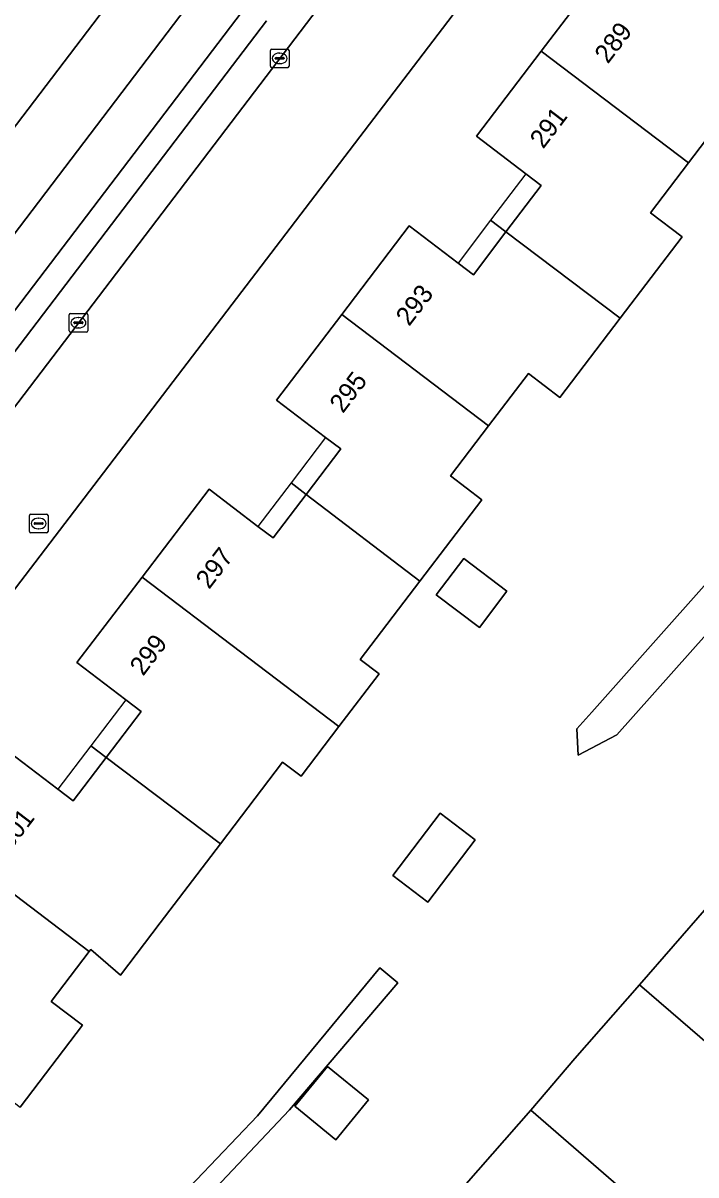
# Model space of a CAD drawing. Extents: x 158472 to 159562, y 388525 to 389606.
# Drawn here: x 158756 to 158792.1, y 388915.3 to 388977 of the extents above; entities that cross this region are included whole.
import ezdxf

# ---------------------------------------------------------------- set-up
doc = ezdxf.new("R2010")
doc.units = 0
for name, color, linetype in [('IMGEO_Berm_groen', 7, 'Continuous'), ('IMGEO_Brandkraan', 7, 'Continuous'), ('IMGEO_Erf', 7, 'Continuous'), ('IMGEO_Kolk', 7, 'Continuous'), ('IMGEO_Pand', 7, 'Continuous'), ('IMGEO_Pand_nummerreeks', 7, 'Continuous'), ('IMGEO_Pand_overbouw', 7, 'Continuous'), ('IMGEO_Parkeervlak_open', 7, 'Continuous'), ('IMGEO_Rijbaan_lokaal_gesloten', 7, 'Continuous'), ('IMGEO_Rijbaan_lokaal_open', 7, 'Continuous'), ('IMGEO_Voetpad_open', 7, 'Continuous')]:
    doc.layers.add(name, color=color, linetype=linetype)

msp = doc.modelspace()

# ---------------------------------------------------------------- linework, layer by layer
at = {"layer": 'IMGEO_Berm_groen'}
msp.add_lwpolyline([(158769.87, 388990.274), (158765.967, 388993.384), (158762.193, 388988.396), (158743.945, 388964.31), (158727.97, 388943.305), (158723.001, 388936.936), (158712.518, 388923.153), (158710.767, 388920.221), (158714.484, 388917.523), (158716.222, 388919.791)], close=True, dxfattribs=at)
at = {"layer": 'IMGEO_Brandkraan'}
for p, q in [((158756.362, 388949.789), (158756.362, 388950.641)), ((158756.437, 388950.715), (158757.289, 388950.715)), ((158756.85, 388950.495), (158756.875, 388950.495)), ((158757.363, 388950.641), (158757.363, 388949.789)), ((158756.621, 388950.209), (158756.621, 388950.221)), ((158757.059, 388950.172), (158756.661, 388950.172)), ((158756.664, 388950.258), (158757.062, 388950.258)), ((158756.873, 388949.935), (158756.848, 388949.935)), ((158757.105, 388950.221), (158757.105, 388950.209)), ((158757.289, 388949.715), (158756.437, 388949.715))]:
    msp.add_line(p, q, dxfattribs=at)
for points in [[(158756.362, 388949.789), (158756.362, 388950.641)], [(158756.437, 388950.715), (158757.289, 388950.715)], [(158757.363, 388950.641), (158757.363, 388949.789)], [(158757.289, 388949.715), (158756.437, 388949.715)]]:
    msp.add_lwpolyline(points, dxfattribs=at)
for centre, radius, start, end in [((158756.439, 388950.639), 0.0765, 91.55205, 178.44795), ((158756.439, 388950.639), 0.0765, 91.55205, 178.44795), ((158757.287, 388950.639), 0.0765, 1.55205, 88.44795), ((158757.287, 388950.639), 0.0765, 1.55205, 88.44795), ((158756.661, 388950.218), 0.0403, 85.87752, 175.75265), ((158756.658, 388950.208), 0.0366, 178.93798, 274.71019), ((158757.062, 388950.215), 0.043, 264.86636, 352.45326), ((158757.066, 388950.22), 0.0386, 1.73085, 96.63898), ((158756.439, 388949.791), 0.0765, 181.55205, 268.44795), ((158756.439, 388949.791), 0.0765, 181.55205, 268.44795), ((158757.287, 388949.791), 0.0765, 271.55205, 358.44795), ((158757.287, 388949.791), 0.0765, 271.55205, 358.44795)]:
    msp.add_arc(centre, radius, start, end, dxfattribs=at)
for centre, major_axis, ratio, start_param, end_param in [((158756.849, 388950.215), (-0.387, 0.002), 0.722429, 4.712389, 7.853982), ((158756.874, 388950.215), (-0.39, 0.002), 0.717154, 1.570796, 4.712389)]:
    msp.add_ellipse(centre, major_axis=major_axis, ratio=ratio, start_param=start_param, end_param=end_param, dxfattribs=at)
at = {"layer": 'IMGEO_Erf'}
for points in [[(158795.974, 388950.739), (158810.599, 388967.168), (158801.457, 388974.099), (158785.644, 388986.089), (158736.904, 388922.269)], [(158755.266, 388937.979), (158757.887, 388935.984), (158758.707, 388935.359), (158760.479, 388937.686), (158762.352, 388940.146), (158761.531, 388940.77), (158758.914, 388942.762), (158762.404, 388947.346), (158765.993, 388952.06), (158768.616, 388950.063), (158769.43, 388949.443), (158771.206, 388951.775), (158773.06, 388954.209), (158772.244, 388954.83), (158769.619, 388956.828), (158773.114, 388961.419), (158776.723, 388966.159), (158779.341, 388964.166), (158780.164, 388963.54), (158781.913, 388965.838), (158783.801, 388968.317), (158782.978, 388968.944), (158780.329, 388970.961), (158783.799, 388975.518), (158787.405, 388980.254)], [(158834.105, 388977.563), (158830.806, 388973.77), (158829.5, 388974.907), (158829.044, 388974.383), (158827.332, 388972.415), (158828.209, 388971.652), (158825.991, 388969.102), (158822.07, 388972.513), (158821.643, 388972.038), (158817.123, 388967.026), (158814.596, 388964.138), (158812.051, 388966.068), (158799.647, 388952.134), (158787.864, 388938.897), (158785.78, 388937.796), (158785.709, 388939.207), (158786.508, 388940.104), (158795.974, 388950.739)], [(158793.858, 388972.374), (158791.703, 388969.543), (158789.659, 388966.858), (158791.351, 388965.57), (158788.034, 388961.214), (158784.805, 388956.973), (158783.117, 388958.259), (158780.979, 388955.451), (158778.937, 388952.768), (158780.618, 388951.488), (158777.302, 388947.133), (158774.101, 388942.928), (158775.11, 388942.16), (158772.959, 388939.334), (158770.937, 388936.677), (158769.941, 388937.435), (158766.609, 388933.058), (158763.377, 388928.813), (158761.244, 388926.012), (158759.651, 388927.389), (158759.572, 388927.285), (158757.534, 388924.608), (158759.21, 388923.332), (158755.875, 388918.951)], [(158779.787, 388914.833), (158783.238, 388918.777), (158785.613, 388921.559), (158789.067, 388925.507), (158792.681, 388929.638)], [(158748.824, 388913.185), (158757.828, 388906.105), (158764.239, 388913.913), (158768.586, 388918.48), (158775.159, 388926.41), (158776.108, 388925.599), (158770.311, 388918.809), (158764.522, 388912.676), (158758.448, 388905.394), (158767.225, 388896.883), (158766.367, 388895.914), (158763.163, 388898.752), (158762.609, 388899.321), (158760.508, 388897.275), (158758.622, 388899.212), (158756.714, 388901.173), (158758.815, 388903.218), (158757.101, 388904.979), (158747.221, 388912.501)]]:
    msp.add_lwpolyline(points, dxfattribs=at)
for points in [[(158780.485, 388944.638), (158778.179, 388946.393), (158779.66, 388948.338), (158781.966, 388946.583)], [(158780.27, 388933.267), (158777.72, 388929.924), (158775.842, 388931.356), (158778.392, 388934.699)], [(158774.536, 388919.331), (158772.785, 388917.2), (158770.595, 388919), (158772.346, 388921.13)]]:
    msp.add_lwpolyline(points, close=True, dxfattribs=at)
at = {"layer": 'IMGEO_Kolk'}
for p, q in [((158769.283, 388974.709), (158769.283, 388975.561)), ((158769.358, 388975.635), (158770.21, 388975.635)), ((158769.542, 388975.129), (158769.542, 388975.141)), ((158769.585, 388975.178), (158769.983, 388975.178)), ((158769.771, 388975.415), (158769.796, 388975.415)), ((158770.026, 388975.141), (158770.026, 388975.129)), ((158770.284, 388975.561), (158770.284, 388974.709)), ((158770.21, 388974.635), (158769.358, 388974.635)), ((158769.98, 388975.092), (158769.582, 388975.092)), ((158769.794, 388974.855), (158769.769, 388974.855)), ((158758.493, 388960.545), (158758.493, 388961.397)), ((158758.568, 388961.471), (158759.42, 388961.471)), ((158758.752, 388960.965), (158758.752, 388960.977)), ((158758.795, 388961.014), (158759.193, 388961.014)), ((158758.981, 388961.251), (158759.006, 388961.251)), ((158759.236, 388960.977), (158759.236, 388960.965)), ((158759.494, 388961.397), (158759.494, 388960.545)), ((158759.42, 388960.471), (158758.568, 388960.471)), ((158759.19, 388960.928), (158758.792, 388960.928)), ((158759.004, 388960.691), (158758.979, 388960.691))]:
    msp.add_line(p, q, dxfattribs=at)
for points in [[(158769.283, 388974.709), (158769.283, 388975.561)], [(158769.358, 388975.635), (158770.21, 388975.635)], [(158770.284, 388975.561), (158770.284, 388974.709)], [(158770.21, 388974.635), (158769.358, 388974.635)], [(158758.493, 388960.545), (158758.493, 388961.397)], [(158758.568, 388961.471), (158759.42, 388961.471)], [(158759.494, 388961.397), (158759.494, 388960.545)], [(158759.42, 388960.471), (158758.568, 388960.471)]]:
    msp.add_lwpolyline(points, dxfattribs=at)
for centre, radius, start, end in [((158769.36, 388975.559), 0.0765, 91.55205, 178.44795), ((158769.36, 388975.559), 0.0765, 91.55205, 178.44795), ((158769.582, 388975.138), 0.0403, 85.87752, 175.75265), ((158769.579, 388975.128), 0.0366, 178.93798, 274.71019), ((158769.983, 388975.135), 0.043, 264.86636, 352.45326), ((158769.987, 388975.14), 0.0386, 1.73085, 96.63898), ((158770.208, 388975.559), 0.0765, 1.55205, 88.44795), ((158770.208, 388975.559), 0.0765, 1.55205, 88.44795), ((158769.36, 388974.711), 0.0765, 181.55205, 268.44795), ((158769.36, 388974.711), 0.0765, 181.55205, 268.44795), ((158770.208, 388974.711), 0.0765, 271.55205, 358.44795), ((158770.208, 388974.711), 0.0765, 271.55205, 358.44795), ((158758.57, 388961.395), 0.0765, 91.55205, 178.44795), ((158758.57, 388961.395), 0.0765, 91.55205, 178.44795), ((158758.792, 388960.974), 0.0403, 85.87752, 175.75265), ((158758.789, 388960.964), 0.0366, 178.93798, 274.71019), ((158759.193, 388960.971), 0.043, 264.86636, 352.45326), ((158759.197, 388960.976), 0.0386, 1.73085, 96.63898), ((158759.418, 388961.395), 0.0765, 1.55205, 88.44795), ((158759.418, 388961.395), 0.0765, 1.55205, 88.44795), ((158758.57, 388960.547), 0.0765, 181.55205, 268.44795), ((158758.57, 388960.547), 0.0765, 181.55205, 268.44795), ((158759.418, 388960.547), 0.0765, 271.55205, 358.44795), ((158759.418, 388960.547), 0.0765, 271.55205, 358.44795)]:
    msp.add_arc(centre, radius, start, end, dxfattribs=at)
for centre, major_axis, ratio, start_param, end_param in [((158769.77, 388975.135), (-0.387, 0.002), 0.722429, 4.712389, 7.853982), ((158769.795, 388975.135), (-0.39, 0.002), 0.717154, 1.570796, 4.712389), ((158758.98, 388960.971), (-0.387, 0.002), 0.722429, 4.712389, 7.853982), ((158759.005, 388960.971), (-0.39, 0.002), 0.717154, 1.570796, 4.712389)]:
    msp.add_ellipse(centre, major_axis=major_axis, ratio=ratio, start_param=start_param, end_param=end_param, dxfattribs=at)
at = {"layer": 'IMGEO_Pand'}
for points in [[(158792.683, 388979.982), (158790.877, 388977.611), (158790.075, 388978.221), (158787.405, 388980.254), (158783.799, 388975.518), (158791.703, 388969.543), (158793.858, 388972.374), (158795.561, 388971.077), (158798.797, 388975.327)], [(158791.703, 388969.543), (158783.799, 388975.518), (158780.329, 388970.961), (158782.978, 388968.944), (158783.801, 388968.317), (158781.913, 388965.838), (158788.034, 388961.214), (158791.351, 388965.57), (158789.659, 388966.858)], [(158781.913, 388965.838), (158780.164, 388963.54), (158779.341, 388964.166), (158776.723, 388966.159), (158773.114, 388961.419), (158780.979, 388955.451), (158783.117, 388958.259), (158784.805, 388956.973), (158788.034, 388961.214)], [(158780.979, 388955.451), (158773.114, 388961.419), (158769.619, 388956.828), (158772.244, 388954.83), (158773.06, 388954.209), (158771.206, 388951.775), (158777.302, 388947.133), (158780.618, 388951.488), (158778.937, 388952.768)], [(158777.302, 388947.133), (158771.206, 388951.775), (158769.43, 388949.443), (158768.616, 388950.063), (158765.993, 388952.06), (158762.404, 388947.346), (158772.959, 388939.334), (158775.11, 388942.16), (158774.101, 388942.928)], [(158778.179, 388946.393), (158780.485, 388944.638), (158781.966, 388946.583), (158779.66, 388948.338)], [(158762.404, 388947.346), (158758.914, 388942.762), (158761.531, 388940.77), (158762.352, 388940.146), (158760.479, 388937.686), (158766.609, 388933.058), (158769.941, 388937.435), (158770.937, 388936.677), (158772.959, 388939.334)], [(158766.609, 388933.058), (158760.479, 388937.686), (158758.707, 388935.359), (158757.887, 388935.984), (158755.266, 388937.979), (158751.679, 388933.268), (158759.572, 388927.285), (158759.651, 388927.389), (158761.244, 388926.012), (158763.377, 388928.813)], [(158775.842, 388931.356), (158777.72, 388929.924), (158780.27, 388933.267), (158778.392, 388934.699)], [(158759.572, 388927.285), (158751.679, 388933.268), (158748.193, 388928.688), (158750.819, 388926.688), (158751.633, 388926.068), (158749.76, 388923.608), (158755.875, 388918.951), (158759.21, 388923.332), (158757.534, 388924.608)], [(158800.815, 388927.052), (158794.9, 388932.21), (158794.825, 388932.124), (158797.077, 388930.154), (158794.915, 388927.683), (158792.681, 388929.638), (158789.067, 388925.507), (158795.023, 388920.378), (158797.036, 388922.679), (158800.903, 388919.296), (158804.714, 388923.652)], [(158789.16, 388913.666), (158793.044, 388910.268), (158793.12, 388910.355), (158797.03, 388914.824), (158793.138, 388918.224), (158795.023, 388920.378), (158789.067, 388925.507), (158785.613, 388921.559), (158783.238, 388918.777)], [(158770.595, 388919), (158772.785, 388917.2), (158774.536, 388919.331), (158772.346, 388921.13)], [(158789.16, 388913.666), (158783.238, 388918.777), (158779.787, 388914.833), (158782.017, 388912.883), (158779.839, 388910.393), (158779.654, 388910.181), (158784.034, 388906.434), (158787.256, 388903.678), (158791.208, 388908.196), (158787.338, 388911.582)]]:
    msp.add_lwpolyline(points, close=True, dxfattribs=at)
at = {"layer": 'IMGEO_Pand_overbouw'}
for points in [[(158781.088, 388966.461), (158781.913, 388965.838), (158783.801, 388968.317), (158782.978, 388968.944)], [(158781.913, 388965.838), (158781.088, 388966.461), (158779.341, 388964.166), (158780.164, 388963.54)], [(158770.391, 388952.396), (158771.206, 388951.775), (158773.06, 388954.209), (158772.244, 388954.83)], [(158771.206, 388951.775), (158770.391, 388952.396), (158768.616, 388950.063), (158769.43, 388949.443)], [(158759.656, 388938.308), (158760.479, 388937.686), (158762.352, 388940.146), (158761.531, 388940.77)], [(158760.479, 388937.686), (158759.656, 388938.308), (158757.887, 388935.984), (158758.707, 388935.359)]]:
    msp.add_lwpolyline(points, close=True, dxfattribs=at)
at = {"layer": 'IMGEO_Parkeervlak_open'}
for points in [[(158749.582, 388948.613), (158772.125, 388978.207)], [(158769.073, 388977.152), (158749.71, 388951.734)]]:
    msp.add_lwpolyline(points, dxfattribs=at)
at = {"layer": 'IMGEO_Rijbaan_lokaal_gesloten'}
for points in [[(158642.3, 388830.16), (158642.462, 388830.323), (158644.297, 388828.539), (158644.976, 388829.209), (158654.546, 388838.744), (158652.694, 388840.633), (158668.364, 388856.424), (158683.318, 388872.712), (158697.002, 388889.186), (158717.328, 388915.448), (158737.178, 388941.567), (158754.114, 388963.852), (158766.121, 388979.65), (158778.301, 388995.677), (158798.192, 389021.851), (158809.433, 389036.528), (158811.777, 389039.288), (158814.069, 389041.449), (158818.297, 389044.22), (158821.97, 389045.718), (158820.551, 389048.928)], [(158822.868, 389043.49), (158821.97, 389045.718), (158818.297, 389044.22), (158814.069, 389041.449), (158811.777, 389039.288), (158809.433, 389036.528), (158798.192, 389021.851), (158778.301, 388995.677), (158766.121, 388979.65), (158754.114, 388963.852), (158737.178, 388941.567), (158717.328, 388915.448), (158697.002, 388889.186), (158683.318, 388872.712), (158668.364, 388856.424), (158652.694, 388840.633), (158654.546, 388838.744), (158654.775, 388838.972), (158671.833, 388856.333), (158672.448, 388857.038), (158674.867, 388859.654), (158677.905, 388862.94)], [(158807.288, 389039.286), (158803.759, 389034.662), (158795.403, 389023.714), (158779.752, 389003.234), (158771.022, 388991.766), (158769.87, 388990.274), (158716.222, 388919.791), (158714.484, 388917.523), (158712.638, 388915.121), (158709.718, 388911.287), (158700.675, 388899.419)], [(158697.058, 388885.041), (158701.938, 388891.173), (158703.321, 388892.993), (158703.594, 388893.363), (158714.902, 388908.014), (158715.242, 388908.465), (158719.808, 388914.514), (158719.947, 388914.699), (158725.749, 388922.405), (158730.616, 388928.858), (158776.401, 388989.012), (158782.009, 388996.219), (158782.277, 388996.564), (158784.893, 389000), (158798.249, 389017.546), (158798.278, 389017.578), (158798.301, 389017.615), (158811.144, 389034.474), (158811.572, 389035.037)]]:
    msp.add_lwpolyline(points, dxfattribs=at)
at = {"layer": 'IMGEO_Rijbaan_lokaal_open'}
for points in [[(158722.397, 388916.043), (158728.63, 388916.382), (158732.572, 388916.597), (158733.954, 388918.407), (158735.98, 388921.059), (158735.987, 388921.069), (158736.904, 388922.269), (158785.644, 388986.089)], [(158776.899, 388984.473), (158772.125, 388978.207), (158749.582, 388948.613), (158747.906, 388946.414), (158731.179, 388924.457), (158730.314, 388923.321)]]:
    msp.add_lwpolyline(points, dxfattribs=at)
at = {"layer": 'IMGEO_Voetpad_open'}
for points in [[(158776.401, 388989.012), (158730.616, 388928.858), (158725.749, 388922.405)], [(158749.71, 388951.734), (158769.073, 388977.152)]]:
    msp.add_lwpolyline(points, dxfattribs=at)
for points in [[(158812.051, 388966.068), (158810.599, 388967.168), (158795.974, 388950.739), (158786.508, 388940.104), (158785.709, 388939.207), (158785.78, 388937.796), (158787.864, 388938.897), (158799.647, 388952.134)], [(158764.522, 388912.676), (158770.311, 388918.809), (158776.108, 388925.599), (158775.159, 388926.41), (158768.586, 388918.48), (158764.239, 388913.913), (158757.828, 388906.105), (158748.824, 388913.185), (158744.91, 388916.164), (158740.932, 388919.193), (158736.904, 388922.269), (158735.987, 388921.069), (158736.081, 388920.982), (158741.732, 388916.68), (158747.221, 388912.501), (158757.101, 388904.979), (158758.815, 388903.218), (158760.689, 388901.293), (158762.609, 388899.321), (158763.163, 388898.752), (158766.367, 388895.914), (158767.225, 388896.883), (158758.448, 388905.394)]]:
    msp.add_lwpolyline(points, close=True, dxfattribs=at)

# ---------------------------------------------------------------- texts
at = {"layer": 'IMGEO_Pand_nummerreeks'}
for s, rotation, p in [('289', 52.71212, (158787.376, 388974.802)), ('291', 52.71212, (158783.907, 388970.246)), ('293', 52.71785, (158776.722, 388960.743)), ('295', 52.71785, (158773.17, 388956.077)), ('297', 52.71785, (158765.999, 388946.652)), ('299', 52.71785, (158762.459, 388942.003)), ('301', 52.71785, (158755.341, 388932.663))]:
    msp.add_text(s, height=1, rotation=rotation, dxfattribs=at).set_placement(p)

doc.saveas('drawing.dxf')
